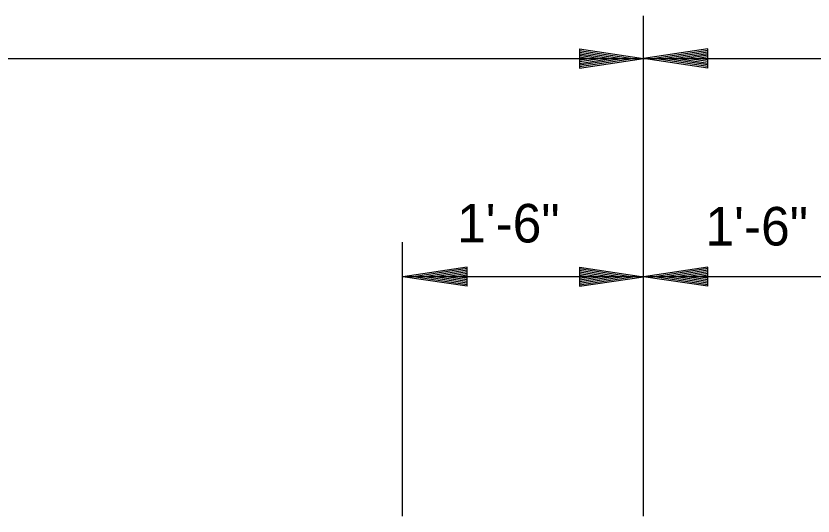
# Model space of a CAD drawing. Extents: x 635488 to 635865, y 290537 to 290973.
# Drawn here: x 635699.81 to 635712.22, y 290613.36 to 290621.14 of the extents above; entities that cross this region are included whole.
import ezdxf

# ---------------------------------------------------------------- set-up
doc = ezdxf.new("R2010")
doc.units = 0
doc.layers.add('Default', color=7, linetype='Continuous')

msp = doc.modelspace()

# ---------------------------------------------------------------- linework, layer by layer
at = {"layer": 'Default'}
for p, q in [((635709.583, 290613.362), (635709.583, 290621.142)), ((635708.585, 290620.63), (635709.585, 290620.48)), ((635708.585, 290620.63), (635708.585, 290620.33)), ((635708.585, 290620.605), (635709.417, 290620.48)), ((635708.585, 290620.58), (635709.245, 290620.48)), ((635708.585, 290620.555), (635709.08, 290620.48)), ((635708.585, 290620.53), (635708.91, 290620.48)), ((635710.584, 290620.63), (635709.585, 290620.48)), ((635710.584, 290620.605), (635709.752, 290620.48)), ((635710.584, 290620.58), (635709.922, 290620.48)), ((635710.584, 290620.555), (635710.089, 290620.48)), ((635710.584, 290620.53), (635710.259, 290620.48)), ((635710.584, 290620.33), (635710.584, 290620.63)), ((635659.586, 290620.481), (635709.583, 290620.481)), ((635708.585, 290620.505), (635708.742, 290620.48)), ((635708.585, 290620.33), (635709.585, 290620.48)), ((635708.585, 290620.433), (635708.91, 290620.48)), ((635708.585, 290620.38), (635709.245, 290620.48)), ((635708.585, 290620.355), (635709.417, 290620.48)), ((635708.585, 290620.405), (635709.08, 290620.48)), ((635708.585, 290620.458), (635708.742, 290620.48)), ((635709.583, 290620.481), (635750.831, 290620.481)), ((635710.584, 290620.33), (635709.585, 290620.48)), ((635710.584, 290620.355), (635709.752, 290620.48)), ((635710.584, 290620.38), (635709.922, 290620.48)), ((635710.584, 290620.405), (635710.089, 290620.48)), ((635710.584, 290620.433), (635710.259, 290620.48)), ((635710.584, 290620.505), (635710.427, 290620.48)), ((635710.584, 290620.458), (635710.427, 290620.48)), ((635705.833, 290613.362), (635705.833, 290617.625)), ((635706.835, 290617.236), (635705.835, 290617.086)), ((635706.835, 290617.211), (635706.002, 290617.086)), ((635706.835, 290617.186), (635706.172, 290617.086)), ((635706.835, 290616.936), (635706.835, 290617.236)), ((635708.585, 290617.236), (635709.585, 290617.086)), ((635708.585, 290617.236), (635708.585, 290616.936)), ((635708.585, 290617.211), (635709.417, 290617.086)), ((635708.585, 290617.186), (635709.245, 290617.086)), ((635710.584, 290617.236), (635709.585, 290617.086)), ((635710.584, 290617.211), (635709.752, 290617.086)), ((635710.584, 290617.186), (635709.922, 290617.086)), ((635710.584, 290616.936), (635710.584, 290617.236)), ((635709.583, 290617.086), (635705.833, 290617.086)), ((635706.835, 290616.936), (635705.835, 290617.086)), ((635706.835, 290616.961), (635706.002, 290617.086)), ((635706.835, 290616.986), (635706.172, 290617.086)), ((635706.835, 290617.161), (635706.34, 290617.086)), ((635706.835, 290617.011), (635706.34, 290617.086)), ((635706.835, 290617.136), (635706.51, 290617.086)), ((635706.835, 290617.038), (635706.51, 290617.086)), ((635706.835, 290617.111), (635706.677, 290617.086)), ((635706.835, 290617.063), (635706.677, 290617.086)), ((635708.585, 290617.161), (635709.08, 290617.086)), ((635708.585, 290617.136), (635708.91, 290617.086)), ((635708.585, 290617.111), (635708.742, 290617.086)), ((635708.585, 290616.936), (635709.585, 290617.086)), ((635708.585, 290617.038), (635708.91, 290617.086)), ((635708.585, 290616.986), (635709.245, 290617.086)), ((635708.585, 290616.961), (635709.417, 290617.086)), ((635708.585, 290617.011), (635709.08, 290617.086)), ((635708.585, 290617.063), (635708.742, 290617.086)), ((635713.333, 290617.086), (635709.583, 290617.086)), ((635710.584, 290616.936), (635709.585, 290617.086)), ((635710.584, 290616.961), (635709.752, 290617.086)), ((635710.584, 290616.986), (635709.922, 290617.086)), ((635710.584, 290617.161), (635710.089, 290617.086)), ((635710.584, 290617.011), (635710.089, 290617.086)), ((635710.584, 290617.136), (635710.259, 290617.086)), ((635710.584, 290617.038), (635710.259, 290617.086)), ((635710.584, 290617.111), (635710.427, 290617.086)), ((635710.584, 290617.063), (635710.427, 290617.086))]:
    msp.add_line(p, q, dxfattribs=at)

# ---------------------------------------------------------------- texts
for p in [(635706.68, 290617.618), (635710.547, 290617.571)]:
    msp.add_text('1\'-6"', height=0.6, dxfattribs=at).set_placement(p)

doc.saveas('drawing.dxf')
